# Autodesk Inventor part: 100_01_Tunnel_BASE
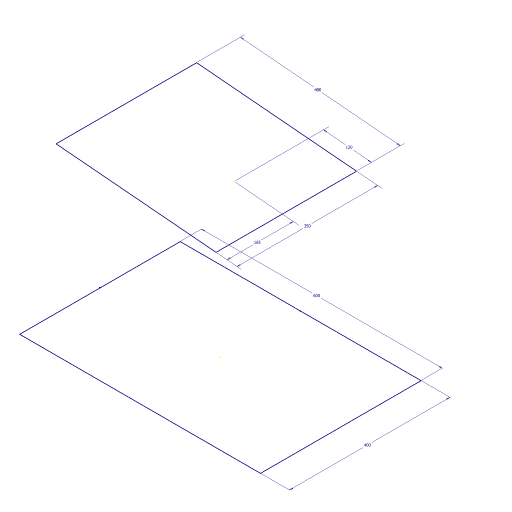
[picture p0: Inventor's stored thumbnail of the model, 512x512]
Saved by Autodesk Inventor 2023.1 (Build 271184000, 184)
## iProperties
Company: Fabian Stasiak CAD Consulting
Category: Autodesk® Inventor® Tutorial Series
Created: 2011-01
Part Number: 100_01_Tunnel_BASE
Material: Steel
Document SubType Name: Konstrukcja blachowa
Designer: F.Stasiak
Density: 7.85 g/cm^3
Sheet Metal Rule: Steel 1.5 mm/Straight
Appearance: Semi-Polished
Catalog Web Link: www.expertbooks.eu
Description: Tunnel BASE
FLATAREA: =<FLAT PATTERN AREA>
Thickness: 1,500 mm
Author: F.Stasiak
Subject: Sheet Metal Design. Basic and Advanced techniques
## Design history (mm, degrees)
sketch "Szkic1"
  geometry: L1 (-300, -200)-(300, -200); L2 (300, -200)-(300, 200); L3 (300, 200)-(-300, 200); L4 (-300, 200)-(-300, -200); 3 further points
  constraints: 8 end point, 2 midpoint, 2 parallel, 1 horizontal, 1 horizontal alignment, 1 perpendicular, 1 vertical alignment
  dimensions: "d0" = 600 distance of L3.end L2.end; "d1" = 400 distance of L2.end L1.end
node "Płaszczyzna konstrukcyjna1"
node "Płaszczyzna konstrukcyjna2"
  node "Oś konstrukcyjna1"
sketch "Szkic2"
  geometry: L1 (-155, 245.138)-(195, 245.138); L2 (195, 245.138)-(195, -154.862); L3 (195, -154.862)-(-155, -154.862); L4 (-155, -154.862)-(-155, 245.138); 1 further point
  constraints: 8 end point, 2 parallel, 1 horizontal, 1 perpendicular
  dimensions: "d4" = 350 distance of L2.end L3.end; "d5" = 400 distance of L1.end L2.end; "d6" = 165 distance from line of L4 point (10, -34.862); "d7" = 120 distance from line of point (10, -34.862) L3
body "Solid4"
other parameters: "Thickness" = 1.5 (derived), "WspółczynnikK" = 4.4, "BendRadius" = 1.5 (= Thickness), "BendReliefWidth" = 1.5 (= Thickness), "BendReliefDepth" = 0.75 (= 0.5 x Thickness), "CornerReliefSize" = 6 (= 4 x Thickness), "OdstępPołączenia" = 0.01, "MinimumRemnant" = 3 (= 2 x Thickness), "TransitionRadius" = 1.5 (= BendRadius), "JacobiRadiusSize" = 1.5 (= BendRadius), "GapSize" = 1.5 (= Thickness), "d3" = 5 deg
